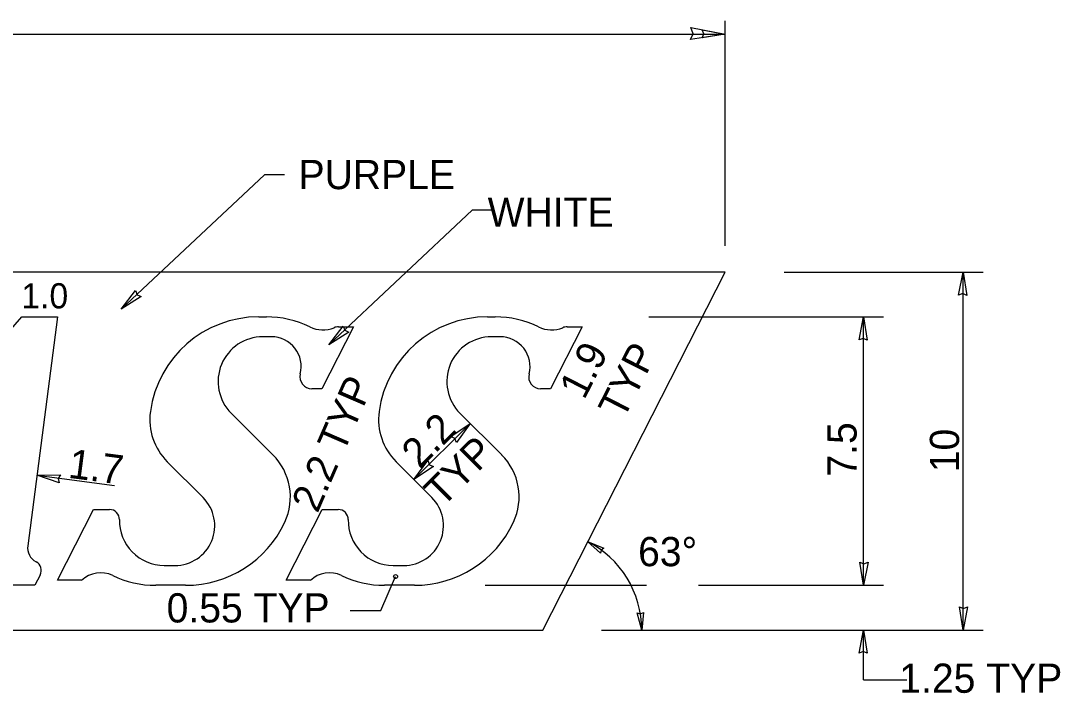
# Model space of a CAD drawing. Extents: x 10268197 to 10269179, y 2141503 to 2142677.
# Drawn here: x 10268621.1 to 10268645.99, y 2142091.07 to 2142107.18 of the extents above; entities that cross this region are included whole.
import ezdxf

# ---------------------------------------------------------------- set-up
doc = ezdxf.new("R2010")
doc.units = 0
for name, color, linetype in [('1', 7, 'Continuous'), ('2', 7, 'Continuous'), ('52', 7, 'Continuous')]:
    doc.layers.add(name, color=color, linetype=linetype)

msp = doc.modelspace()

# ---------------------------------------------------------------- linework, layer by layer
at = {"layer": '1'}
for p, q in [((10268637.974, 2142101.785), (10268637.974, 2142107.18)), ((10268596.278, 2142106.859), (10268637.974, 2142106.859)), ((10268639.38, 2142101.158), (10268644.145, 2142101.158)), ((10268643.668, 2142092.583), (10268643.668, 2142101.158)), ((10268636.139, 2142100.086), (10268641.762, 2142100.086)), ((10268641.286, 2142093.655), (10268641.286, 2142100.086)), ((10268630.518, 2142096.186), (10268631.866, 2142097.533)), ((10268621.489, 2142096.29), (10268623.347, 2142096.048)), ((10268629.728, 2142093.047), (10268630.078, 2142093.864)), ((10268632.221, 2142093.655), (10268636.084, 2142093.655)), ((10268637.328, 2142093.655), (10268641.762, 2142093.655)), ((10268628.988, 2142093.047), (10268629.728, 2142093.047)), ((10268635.011, 2142092.583), (10268644.145, 2142092.583)), ((10268641.286, 2142091.393), (10268641.286, 2142092.583)), ((10268641.286, 2142091.393), (10268642.323, 2142091.393))]:
    msp.add_line(p, q, dxfattribs=at)
for points in [[(10268627.416, 2142103.491), (10268626.938, 2142103.491), (10268623.507, 2142100.269)], [(10268632.389, 2142102.64), (10268631.911, 2142102.64), (10268628.479, 2142099.417)]]:
    msp.add_lwpolyline(points, dxfattribs=at)
msp.add_circle((10268630.077, 2142093.864), 0.0476, dxfattribs=at)
msp.add_arc((10268633.59, 2142092.583), 2.382, 0, 63.0012, dxfattribs=at)
at = {"layer": '2'}
for p, q in [((10268637.974, 2142101.158), (10268612.125, 2142101.158)), ((10268633.605, 2142092.582), (10268637.974, 2142101.158)), ((10268616.262, 2142094.49), (10268621.126, 2142100.086)), ((10268621.126, 2142100.086), (10268621.983, 2142100.086)), ((10268621.983, 2142100.086), (10268621.269, 2142094.604)), ((10268626.802, 2142100.086), (10268626.983, 2142100.086)), ((10268632.28, 2142100.086), (10268632.461, 2142100.086)), ((10268629.068, 2142099.847), (10268628.311, 2142098.362)), ((10268628.712, 2142099.847), (10268629.068, 2142099.847)), ((10268634.547, 2142099.847), (10268633.79, 2142098.362)), ((10268634.189, 2142099.847), (10268634.547, 2142099.847)), ((10268627.102, 2142099.609), (10268626.9, 2142099.609)), ((10268632.582, 2142099.609), (10268632.377, 2142099.609)), ((10268628.311, 2142098.362), (10268628.072, 2142098.362)), ((10268633.79, 2142098.362), (10268633.551, 2142098.362)), ((10268626.141, 2142097.78), (10268627.139, 2142096.781)), ((10268631.619, 2142097.78), (10268632.618, 2142096.781)), ((10268625.468, 2142095.757), (10268624.611, 2142096.613)), ((10268630.946, 2142095.757), (10268630.089, 2142096.613)), ((10268621.98, 2142093.774), (10268622.845, 2142095.471)), ((10268622.845, 2142095.471), (10268623.227, 2142095.471)), ((10268627.458, 2142093.774), (10268628.323, 2142095.471)), ((10268628.323, 2142095.471), (10268628.706, 2142095.471)), ((10268624.536, 2142094.131), (10268624.793, 2142094.131)), ((10268630.017, 2142094.131), (10268630.273, 2142094.131)), ((10268621.568, 2142093.899), (10268621.442, 2142093.654)), ((10268622.559, 2142093.774), (10268621.98, 2142093.774)), ((10268628.037, 2142093.774), (10268627.458, 2142093.774)), ((10268621.442, 2142093.654), (10268619.06, 2142093.654)), ((10268625.05, 2142093.654), (10268624.334, 2142093.654)), ((10268630.528, 2142093.654), (10268629.812, 2142093.654)), ((10268611.339, 2142092.582), (10268633.605, 2142092.582))]:
    msp.add_line(p, q, dxfattribs=at)
for centre, radius, start, end in [((10268626.801, 2142097.466), 2.62, 90, 172.3089), ((10268626.982, 2142097.704), 2.382, 64.0896, 90), ((10268632.28, 2142097.466), 2.62, 90, 172.3089), ((10268632.461, 2142097.704), 2.382, 64.0896, 90), ((10268628.335, 2142100.489), 0.715, 244.0896, 292.0347), ((10268628.71, 2142099.562), 0.286, 90, 112.0347), ((10268633.814, 2142100.489), 0.715, 244.0896, 292.0347), ((10268634.189, 2142099.562), 0.286, 90, 112.0347), ((10268626.899, 2142098.537), 1.072, 90, 225), ((10268627.103, 2142098.895), 0.715, 345.6915, 90), ((10268632.377, 2142098.537), 1.072, 90, 225), ((10268632.582, 2142098.895), 0.715, 345.6915, 90), ((10268628.073, 2142098.647), 0.286, 165.6915, 270), ((10268633.551, 2142098.647), 0.286, 165.6915, 270), ((10268625.621, 2142097.625), 1.429, 172.3089, 225), ((10268631.1, 2142097.625), 1.429, 172.3089, 225), ((10268626.129, 2142095.77), 1.429, 334.95, 45), ((10268631.607, 2142095.77), 1.429, 334.95, 45), ((10268624.794, 2142095.083), 0.953, 270, 45), ((10268630.272, 2142095.083), 0.953, 270, 45), ((10268623.227, 2142095.233), 0.238, 358.6664, 90), ((10268624.537, 2142095.203), 1.072, 178.6665, 270), ((10268628.706, 2142095.233), 0.238, 358.6664, 90), ((10268630.016, 2142095.203), 1.072, 178.6665, 270), ((10268625.05, 2142096.274), 2.62, 270, 334.95), ((10268630.528, 2142096.274), 2.62, 270, 334.95), ((10268621.647, 2142094.554), 0.381, 172.5884, 241.8673), ((10268621.355, 2142094.008), 0.238, 332.9784, 61.8673), ((10268623.015, 2142093.287), 0.667, 64.3795, 133.1892), ((10268624.333, 2142096.036), 2.382, 244.3795, 270), ((10268628.493, 2142093.287), 0.667, 64.3795, 133.1892), ((10268629.812, 2142096.036), 2.382, 244.3795, 270)]:
    msp.add_arc(centre, radius, start, end, dxfattribs=at)
at = {"layer": '52'}
for points in [[(10268637.974, 2142106.859), (10268637.139, 2142106.728), (10268637.202, 2142106.87), (10268637.145, 2142107.019)], [(10268637.974, 2142106.859), (10268637.418, 2142106.771), (10268637.46, 2142106.867), (10268637.421, 2142106.966)], [(10268643.668, 2142101.158), (10268643.755, 2142100.601), (10268643.66, 2142100.643), (10268643.561, 2142100.605)], [(10268623.507, 2142100.269), (10268623.852, 2142100.714), (10268623.887, 2142100.616), (10268623.983, 2142100.57)], [(10268641.286, 2142100.086), (10268641.374, 2142099.53), (10268641.278, 2142099.571), (10268641.179, 2142099.533)], [(10268628.479, 2142099.417), (10268628.825, 2142099.862), (10268628.86, 2142099.764), (10268628.955, 2142099.717)], [(10268631.866, 2142097.533), (10268631.534, 2142097.077), (10268631.497, 2142097.174), (10268631.4, 2142097.217)], [(10268630.518, 2142096.186), (10268630.85, 2142096.641), (10268630.888, 2142096.544), (10268630.985, 2142096.501)], [(10268621.489, 2142096.29), (10268622.052, 2142096.305), (10268621.998, 2142096.216), (10268622.023, 2142096.112)], [(10268634.671, 2142094.705), (10268635.062, 2142094.545), (10268634.998, 2142094.5), (10268634.984, 2142094.422)], [(10268641.286, 2142093.655), (10268641.198, 2142094.211), (10268641.294, 2142094.169), (10268641.393, 2142094.207)], [(10268635.972, 2142092.583), (10268635.866, 2142092.992), (10268635.941, 2142092.968), (10268636.012, 2142093.003)], [(10268643.668, 2142092.583), (10268643.58, 2142093.139), (10268643.676, 2142093.097), (10268643.775, 2142093.135)], [(10268641.286, 2142092.583), (10268641.374, 2142092.026), (10268641.278, 2142092.068), (10268641.179, 2142092.03)]]:
    msp.add_lwpolyline(points, close=True, dxfattribs=at)

# ---------------------------------------------------------------- texts
at = {"layer": '1'}
for s, height, p in [('PURPLE', 0.7, (10268627.754, 2142103.146)), ('WHITE', 0.7, (10268632.282, 2142102.244)), ('1.0', 0.6037, (10268621.115, 2142100.289)), ('63°', 0.7, (10268635.885, 2142094.112)), ('0.55 TYP', 0.7, (10268624.595, 2142092.764)), ('1.25 TYP', 0.7, (10268642.141, 2142091.079))]:
    msp.add_text(s, height=height, dxfattribs=at).set_placement(p)
for s, rotation, p in [('1.9', 63, (10268634.594, 2142098.079)), ('TYP', 63, (10268635.53, 2142097.603)), ('2.2 TYP', 66.578, (10268628.207, 2142095.362)), ('2.2', 45, (10268630.652, 2142096.429)), ('7.5', 90, (10268641.118, 2142096.259)), ('10', 90, (10268643.572, 2142096.364)), ('TYP', 45, (10268631.198, 2142095.504)), ('1.7', 352.5994, (10268622.218, 2142096.233))]:
    msp.add_text(s, height=0.7, rotation=rotation, dxfattribs=at).set_placement(p)

doc.saveas('drawing.dxf')
